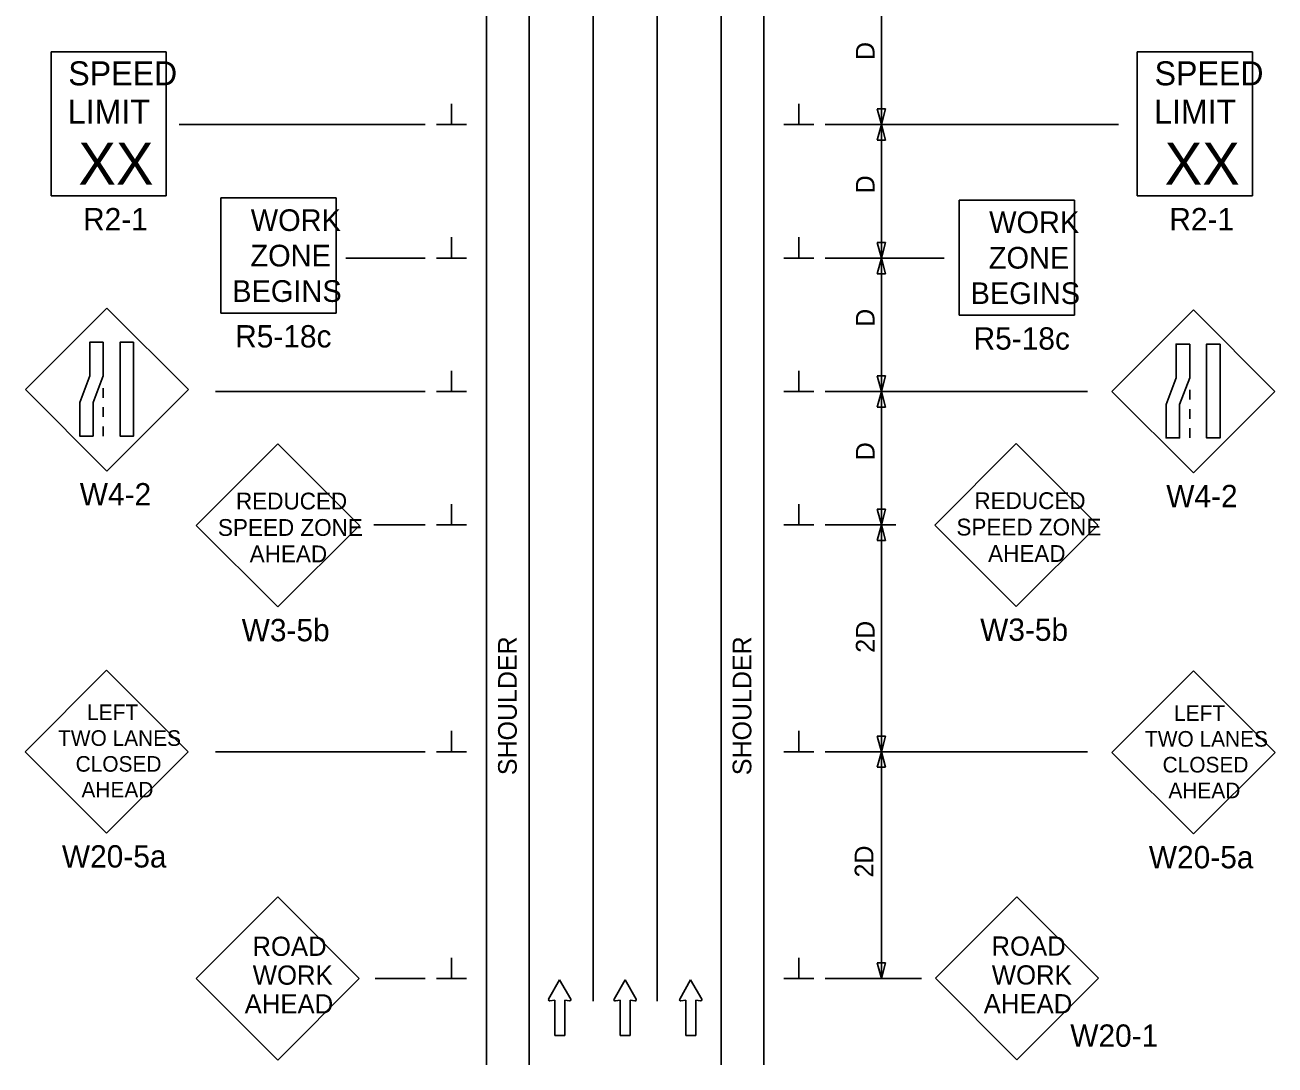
# Model space of a CAD drawing. Extents: x 16731 to 18475, y 5523 to 6928.
# Drawn here: x 16743.7 to 17212.1, y 6059.8 to 6449.5 of the extents above; entities that cross this region are included whole.
import ezdxf

# ---------------------------------------------------------------- set-up
doc = ezdxf.new("R2010")
doc.units = 0
for name, color, linetype in [('ALI_LEGAL_EX', 7, 'Continuous'), ('MT_SCRATCH_LEVEL_E', 7, 'Continuous'), ('PAVT_EDGE_EX', 7, 'Continuous'), ('TRAFFIC_SIGNS_PR', 7, 'Continuous'), ('TYPICAL_TEXT_DIMEN_PR', 7, 'Continuous')]:
    doc.layers.add(name, color=color, linetype=linetype)

msp = doc.modelspace()

# ---------------------------------------------------------------- linework, layer by layer
at = {"layer": 'ALI_LEGAL_EX'}
for p, q in [((16956.63, 6927.83), (16956.63, 6083.69)), ((16980.63, 6927.83), (16980.63, 6083.69))]:
    msp.add_line(p, q, dxfattribs=at)
for points in [[(16956.63, 6427.83), (16956.63, 6402.83)], [(16980.63, 6427.83), (16980.63, 6402.83)], [(16956.63, 6327.83), (16956.63, 6302.83)], [(16980.63, 6327.83), (16980.63, 6302.83)], [(16956.63, 6227.83), (16956.63, 6202.83)], [(16980.63, 6227.83), (16980.63, 6202.83)], [(16956.63, 6127.83), (16956.63, 6102.83)], [(16980.63, 6127.83), (16980.63, 6102.83)]]:
    msp.add_lwpolyline(points, dxfattribs=at)
at = {"layer": 'MT_SCRATCH_LEVEL_E'}
for p, q in [((16944.07, 6091.71), (16939.96, 6084.47)), ((16948.22, 6084.47), (16944.07, 6091.71)), ((16968.6, 6091.71), (16964.49, 6084.47)), ((16972.75, 6084.47), (16968.6, 6091.71)), ((16993.16, 6091.71), (16989.05, 6084.47)), ((16997.31, 6084.47), (16993.16, 6091.71)), ((16940.44, 6083.79), (16942.22, 6084.1)), ((16942.22, 6084.1), (16942.22, 6070.84)), ((16945.96, 6070.84), (16945.96, 6084.1)), ((16945.96, 6084.1), (16947.74, 6083.79)), ((16964.97, 6083.79), (16966.75, 6084.1)), ((16966.75, 6084.1), (16966.75, 6070.84)), ((16970.49, 6070.84), (16970.49, 6084.1)), ((16970.49, 6084.1), (16972.27, 6083.79)), ((16989.53, 6083.79), (16991.31, 6084.1)), ((16991.31, 6084.1), (16991.31, 6070.84)), ((16995.05, 6070.84), (16995.05, 6084.1)), ((16995.05, 6084.1), (16996.83, 6083.79)), ((16942.22, 6070.84), (16945.96, 6070.84)), ((16966.75, 6070.84), (16970.49, 6070.84)), ((16991.31, 6070.84), (16995.05, 6070.84))]:
    msp.add_line(p, q, dxfattribs=at)
for centre, start, end in [((16940.37, 6084.25), 150.4248, 279.9638), ((16947.81, 6084.25), 260.0362, 29.7731), ((16964.9, 6084.25), 150.4248, 279.9638), ((16972.34, 6084.25), 260.0362, 29.7731), ((16989.46, 6084.25), 150.4248, 279.9638), ((16996.9, 6084.25), 260.0362, 29.7731)]:
    msp.add_arc(centre, 0.463, start, end, dxfattribs=at)
at = {"layer": 'PAVT_EDGE_EX'}
for p, q in [((16916.63, 6919.19), (16916.63, 6059.77)), ((16932.63, 6919.19), (16932.63, 6059.77)), ((17004.63, 6919.19), (17004.63, 6059.77)), ((17020.63, 6919.19), (17020.63, 6059.77))]:
    msp.add_line(p, q, dxfattribs=at)
at = {"layer": 'TRAFFIC_SIGNS_PR'}
for p, q in [((16753.48, 6439.44), (16796.68, 6439.44)), ((16753.48, 6385.44), (16753.48, 6439.44)), ((16796.68, 6385.44), (16796.68, 6439.44)), ((17160.53, 6439.44), (17203.73, 6439.44)), ((17160.53, 6385.44), (17160.53, 6439.44)), ((17203.73, 6385.44), (17203.73, 6439.44)), ((16753.48, 6385.44), (16796.68, 6385.44)), ((16817.08, 6341.54), (16817.08, 6384.74)), ((16817.08, 6384.74), (16860.28, 6384.74)), ((16860.28, 6341.54), (16860.28, 6384.74)), ((17160.53, 6385.44), (17203.73, 6385.44)), ((17093.78, 6340.73), (17093.78, 6383.93)), ((17093.78, 6383.93), (17136.98, 6383.93)), ((17136.98, 6340.73), (17136.98, 6383.93)), ((16774.44, 6343.44), (16743.89, 6312.89)), ((16804.98, 6312.89), (16774.44, 6343.44)), ((17181.56, 6342.76), (17151.01, 6312.21)), ((17212.11, 6312.21), (17181.56, 6342.76)), ((16817.08, 6341.54), (16860.28, 6341.54)), ((17093.78, 6340.73), (17136.98, 6340.73)), ((16743.89, 6312.89), (16774.44, 6282.35)), ((16773.03, 6313.45), (16773.03, 6309.85)), ((16774.44, 6282.35), (16804.98, 6312.89)), ((17151.01, 6312.21), (17181.56, 6281.67)), ((17180.16, 6312.77), (17180.16, 6309.17)), ((17181.56, 6281.67), (17212.11, 6312.21)), ((16773.03, 6306.25), (16773.03, 6302.65)), ((17180.16, 6305.57), (17180.16, 6301.97)), ((16773.03, 6299.05), (16773.03, 6295.45)), ((17180.16, 6298.37), (17180.16, 6294.77)), ((16838.48, 6292.53), (16807.93, 6261.99)), ((16869.03, 6261.99), (16838.48, 6292.53)), ((17115.19, 6292.68), (17084.64, 6262.14)), ((17145.74, 6262.14), (17115.19, 6292.68)), ((16807.93, 6261.99), (16838.48, 6231.44)), ((16838.48, 6231.44), (16869.03, 6261.99)), ((17084.64, 6262.14), (17115.19, 6231.59)), ((17115.19, 6231.59), (17145.74, 6262.14)), ((16774.28, 6207.74), (16743.73, 6177.19)), ((16804.82, 6177.19), (16774.28, 6207.74)), ((17181.59, 6207.44), (17151.04, 6176.89)), ((17212.14, 6176.89), (17181.59, 6207.44)), ((16743.73, 6177.19), (16774.28, 6146.64)), ((16774.28, 6146.64), (16804.82, 6177.19)), ((17151.04, 6176.89), (17181.59, 6146.34)), ((17181.59, 6146.34), (17212.14, 6176.89)), ((16838.46, 6122.73), (16807.91, 6092.19)), ((16869.01, 6092.19), (16838.46, 6122.73)), ((17115.41, 6122.79), (17084.87, 6092.25)), ((17145.96, 6092.25), (17115.41, 6122.79)), ((16807.91, 6092.19), (16838.46, 6061.64)), ((16838.46, 6061.64), (16869.01, 6092.19)), ((17084.87, 6092.25), (17115.41, 6061.7)), ((17115.41, 6061.7), (17145.96, 6092.25))]:
    msp.add_line(p, q, dxfattribs=at)
for points in [[(16773.03, 6330.6), (16773.03, 6318.02), (16769.27, 6308.03), (16769.27, 6295.45), (16764.22, 6295.45), (16764.22, 6308.03), (16767.98, 6318.02), (16767.98, 6330.6)], [(16784.44, 6330.6), (16784.44, 6295.45), (16779.38, 6295.45), (16779.38, 6330.6)], [(17180.16, 6329.92), (17180.16, 6317.34), (17176.39, 6307.35), (17176.39, 6294.77), (17171.34, 6294.77), (17171.34, 6307.35), (17175.1, 6317.34), (17175.1, 6329.92)], [(17191.56, 6329.92), (17191.56, 6294.77), (17186.5, 6294.77), (17186.5, 6329.92)]]:
    msp.add_lwpolyline(points, close=True, dxfattribs=at)
at = {"layer": 'TYPICAL_TEXT_DIMEN_PR'}
for p, q in [((17064.63, 6462.19), (17064.63, 6412.19)), ((16903.51, 6412.19), (16903.51, 6419.97)), ((17033.76, 6412.19), (17033.76, 6419.97)), ((17064.63, 6412.19), (17063.06, 6418.05)), ((17063.06, 6418.05), (17064.63, 6418.05)), ((17064.63, 6418.05), (17066.2, 6418.05)), ((17066.2, 6418.05), (17064.63, 6412.19)), ((16801.56, 6412.19), (16893.63, 6412.19)), ((16897.88, 6412.19), (16909.13, 6412.19)), ((17039.38, 6412.19), (17028.13, 6412.19)), ((17043.63, 6412.19), (17153.45, 6412.19)), ((17063.06, 6406.33), (17064.63, 6412.19)), ((17064.63, 6412.19), (17064.63, 6362.19)), ((17064.63, 6412.19), (17066.2, 6406.33)), ((17064.63, 6406.33), (17063.06, 6406.33)), ((17066.2, 6406.33), (17064.63, 6406.33)), ((16903.51, 6362.19), (16903.51, 6369.97)), ((17033.76, 6362.19), (17033.76, 6369.97)), ((17064.63, 6362.19), (17063.06, 6368.05)), ((17063.06, 6368.05), (17064.63, 6368.05)), ((17064.63, 6368.05), (17066.2, 6368.05)), ((17066.2, 6368.05), (17064.63, 6362.19)), ((16893.63, 6362.19), (16863.93, 6362.19)), ((16897.88, 6362.19), (16909.13, 6362.19)), ((17039.38, 6362.19), (17028.13, 6362.19)), ((17043.63, 6362.19), (17088.17, 6362.19)), ((17063.06, 6356.33), (17064.63, 6362.19)), ((17064.63, 6362.19), (17066.2, 6356.33)), ((17064.63, 6362.19), (17064.63, 6312.19)), ((17064.63, 6356.33), (17063.06, 6356.33)), ((17066.2, 6356.33), (17064.63, 6356.33)), ((16903.51, 6312.19), (16903.51, 6319.97)), ((17033.76, 6312.19), (17033.76, 6319.97)), ((17064.63, 6312.19), (17063.06, 6318.05)), ((17063.06, 6318.05), (17064.63, 6318.05)), ((17064.63, 6318.05), (17066.2, 6318.05)), ((17066.2, 6318.05), (17064.63, 6312.19)), ((16893.63, 6312.19), (16815.08, 6312.19)), ((16897.88, 6312.19), (16909.13, 6312.19)), ((17039.38, 6312.19), (17028.13, 6312.19)), ((17043.63, 6312.19), (17141.92, 6312.19)), ((17063.06, 6306.33), (17064.63, 6312.19)), ((17064.63, 6312.19), (17064.63, 6262.19)), ((17064.63, 6312.19), (17066.2, 6306.33)), ((17064.63, 6306.33), (17063.06, 6306.33)), ((17066.2, 6306.33), (17064.63, 6306.33)), ((17064.63, 6272.19), (17064.63, 6177.19)), ((16903.51, 6262.19), (16903.51, 6269.97)), ((17033.76, 6262.19), (17033.76, 6269.97)), ((17064.63, 6262.19), (17063.06, 6268.05)), ((17063.06, 6268.05), (17064.63, 6268.05)), ((17064.63, 6268.05), (17066.2, 6268.05)), ((17066.2, 6268.05), (17064.63, 6262.19)), ((16874.41, 6262.19), (16893.63, 6262.19)), ((16897.88, 6262.19), (16909.13, 6262.19)), ((17039.38, 6262.19), (17028.13, 6262.19)), ((17043.63, 6262.19), (17070.11, 6262.19)), ((17063.06, 6256.33), (17064.63, 6262.19)), ((17064.63, 6262.19), (17066.2, 6256.33)), ((17064.63, 6256.33), (17063.06, 6256.33)), ((17066.2, 6256.33), (17064.63, 6256.33)), ((16903.51, 6177.19), (16903.51, 6184.97)), ((17033.76, 6177.19), (17033.76, 6184.97)), ((17064.63, 6177.19), (17063.06, 6183.05)), ((17063.06, 6183.05), (17064.63, 6183.05)), ((17064.63, 6183.05), (17066.2, 6183.05)), ((17066.2, 6183.05), (17064.63, 6177.19)), ((16893.63, 6177.19), (16815.08, 6177.19)), ((16897.88, 6177.19), (16909.13, 6177.19)), ((17039.38, 6177.19), (17028.13, 6177.19)), ((17043.63, 6177.19), (17141.92, 6177.19)), ((17063.06, 6171.33), (17064.63, 6177.19)), ((17064.63, 6177.19), (17064.63, 6092.19)), ((17064.63, 6177.19), (17066.2, 6171.33)), ((17064.63, 6171.33), (17063.06, 6171.33)), ((17066.2, 6171.33), (17064.63, 6171.33)), ((16903.51, 6092.19), (16903.51, 6099.97)), ((17033.76, 6092.19), (17033.76, 6099.97)), ((17064.63, 6092.19), (17063.06, 6098.05)), ((17063.06, 6098.05), (17064.63, 6098.05)), ((17064.63, 6098.05), (17066.2, 6098.05)), ((17066.2, 6098.05), (17064.63, 6092.19)), ((16893.63, 6092.19), (16874.91, 6092.19)), ((16897.88, 6092.19), (16909.13, 6092.19)), ((17039.38, 6092.19), (17028.13, 6092.19)), ((17043.63, 6092.19), (17079.63, 6092.19))]:
    msp.add_line(p, q, dxfattribs=at)

# ---------------------------------------------------------------- texts
at = {"layer": 'TRAFFIC_SIGNS_PR'}
for s, height, p in [('SPEED', 9, (16759.96, 6426.91)), ('SPEED', 9, (17167.02, 6426.91)), ('LIMIT', 9, (16759.78, 6412.51)), ('LIMIT', 9, (17166.83, 6412.51)), ('XX', 15.785, (16763.73, 6389.67)), ('XX', 15.785, (17170.78, 6389.67)), ('R2-1', 8.37, (16765.49, 6372.57)), ('WORK', 8.119, (16828.33, 6372.32)), ('WORK', 8.119, (17105.03, 6371.52)), ('R2-1', 8.37, (17172.54, 6372.57)), ('ZONE', 8.119, (16828.2, 6359.04)), ('ZONE', 8.119, (17104.89, 6358.23)), ('BEGINS', 8.119, (16821.37, 6345.75)), ('BEGINS', 8.119, (17098.06, 6344.95)), ('R5-18c', 8.37, (16822.49, 6328.67)), ('R5-18c', 8.37, (17099.19, 6327.86)), ('W4-2', 8.37, (16764.26, 6269.48)), ('W4-2', 8.37, (17171.39, 6268.8)), ('REDUCED', 6.3, (16822.79, 6267.96)), ('REDUCED', 6.3, (17099.5, 6268.11)), ('SPEED ZONE', 6.3, (16816.03, 6258.06)), ('SPEED ZONE', 6.3, (17092.75, 6258.21)), ('AHEAD', 6.3, (16827.92, 6248.16)), ('AHEAD', 6.3, (17104.63, 6248.31)), ('W3-5b', 8.37, (16824.93, 6218.57)), ('W3-5b', 8.37, (17101.64, 6218.72)), ('LEFT', 5.85, (16767, 6189.04)), ('LEFT', 5.85, (17174.32, 6188.74)), ('TWO LANES', 5.85, (16756.12, 6179.37)), ('TWO LANES', 5.85, (17163.43, 6179.07)), ('CLOSED', 5.85, (16762.7, 6169.69)), ('CLOSED', 5.85, (17170.02, 6169.39)), ('AHEAD', 5.85, (16764.89, 6160.02)), ('AHEAD', 5.85, (17172.2, 6159.72)), ('W20-5a', 8.37, (16757.56, 6133.77)), ('W20-5a', 8.37, (17164.87, 6133.47)), ('ROAD', 7.2, (17105.9, 6100.73)), ('ROAD', 7.2, (16828.94, 6100.66)), ('WORK', 7.2, (16829.07, 6089.86)), ('WORK', 7.2, (17106.02, 6089.93)), ('AHEAD', 7.2, (16826.04, 6079.07)), ('AHEAD', 7.2, (17102.99, 6079.12)), ('W20-1', 8.37, (17135.42, 6066.6))]:
    msp.add_text(s, height=height, dxfattribs=at).set_placement(p)
at = {"layer": 'TYPICAL_TEXT_DIMEN_PR'}
for s, p in [('D', (17062.08, 6436.41)), ('D', (17062.08, 6386.41)), ('D', (17062.08, 6336.41)), ('D', (17062.08, 6286.41)), ('2D', (17062.08, 6214.26)), ('SHOULDER', (16928.01, 6168.39)), ('SHOULDER', (17015.91, 6168.39)), ('2D', (17061.64, 6130.05))]:
    msp.add_text(s, height=7, rotation=90, dxfattribs=at).set_placement(p)

doc.saveas('drawing.dxf')
